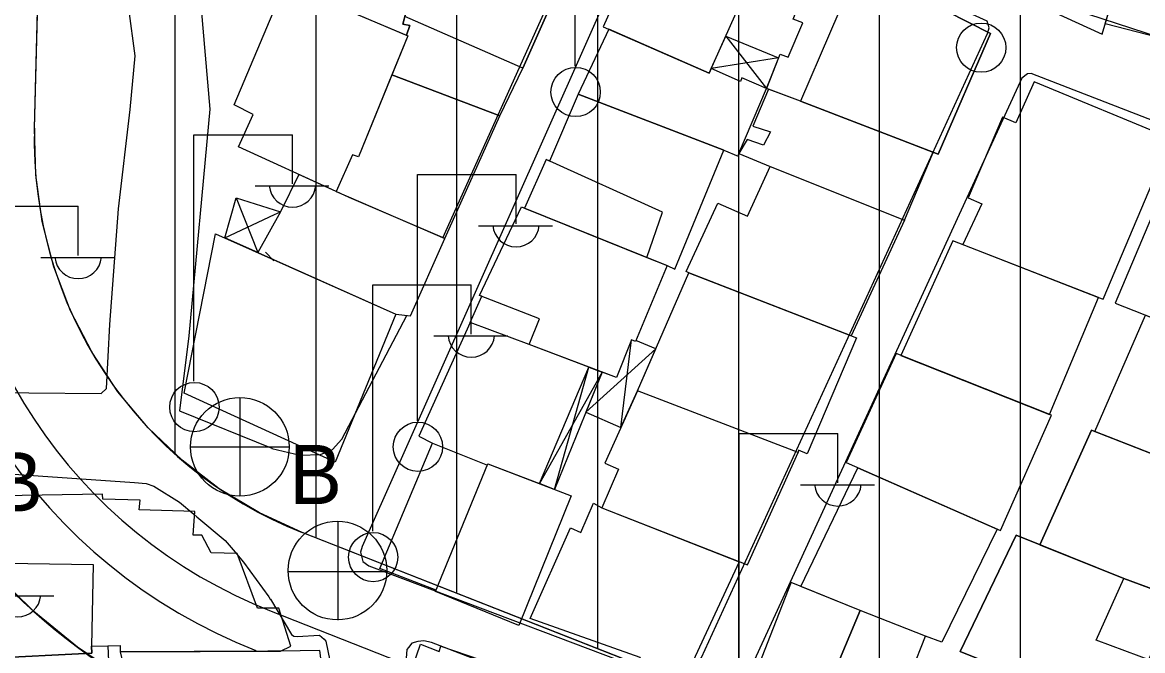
# Model space of a CAD drawing. Extents: x 417997 to 421451, y 4451742 to 4455216.
# Drawn here: x 419134.5 to 419214.1, y 4452750.1 to 4452794.7 of the extents above; entities that cross this region are included whole.
import ezdxf

# ---------------------------------------------------------------- set-up
doc = ezdxf.new("R2010")
doc.units = 0
for name, color, linetype in [('ADAKENARI', 7, 'Continuous'), ('B_Mesken', 7, 'Continuous'), ('B_Sundurma', 7, 'Continuous'), ('B_Teras', 7, 'Continuous'), ('KALDIRIM', 7, 'Continuous'), ('PL_KON_MEV_350', 7, 'Continuous'), ('S_Elektrik_Diregi', 7, 'Continuous'), ('S_Rogar_Kapagi', 7, 'Continuous'), ('S_Rogar_Kapagi_Buski', 7, 'Continuous'), ('TR_ORTAYOGUNKONUT', 7, 'Continuous'), ('Yol_Sose', 7, 'Continuous')]:
    doc.layers.add(name, color=color, linetype=linetype)

msp = doc.modelspace()

# ---------------------------------------------------------------- linework, layer by layer
at = {"layer": 'ADAKENARI'}
for p, q in [((419135.391, 4452787.233), (419139.641, 4452947.996)), ((419135.391, 4452787.233), (419139.641, 4452947.996)), ((419277.123, 4452710.286), (419154.406, 4452758.519)), ((419277.123, 4452710.286), (419154.406, 4452758.519))]:
    msp.add_line(p, q, dxfattribs=at)
for centre, radius, start in [((419165.38, 4452786.44), 30, 178.48545), ((419165.38, 4452786.44), 30, 178.48545), ((419165.38, 4452786.439), 44.999, 207.76938), ((419165.38, 4452786.439), 44.999, 207.76938)]:
    msp.add_arc(centre, radius, start, 248.54329, dxfattribs=at)
at = {"layer": 'B_Mesken'}
for points in [[(419203.777, 4452797.297), (419211.188, 4452793.894), (419215.412, 4452808.094), (419212.257, 4452809.448), (419211.214, 4452807.034), (419208.836, 4452808.231)], [(419221.91, 4452805.106), (419218.926, 4452792.696), (419211.405, 4452794.624), (419215.412, 4452808.094)], [(419157.817, 4452806.337), (419154.508, 4452796.927), (419161.797, 4452793.834), (419162.036, 4452794.503), (419161.552, 4452794.6), (419163.891, 4452803.407)], [(419175.774, 4452794.422), (419183.297, 4452791.138), (419187.756, 4452801.095), (419180.374, 4452804.709)], [(419170.076, 4452791.478), (419173.588, 4452799.428), (419173.29, 4452799.556), (419170.589, 4452800.51), (419163.891, 4452803.407), (419161.698, 4452795.15), (419161.552, 4452794.6), (419162.036, 4452794.503), (419161.797, 4452793.834), (419161.913, 4452793.785), (419160.775, 4452791.003), (419168.433, 4452788.097), (419170.076, 4452791.478), (419173.588, 4452799.428)], [(419189.784, 4452789.128), (419187.368, 4452790.033), (419188.326, 4452792.486), (419188.913, 4452792.259), (419189.94, 4452794.694), (419189.25, 4452794.955), (419191.132, 4452799.687), (419193.712, 4452798.305), (419193.893, 4452798.729), (419203.277, 4452793.934), (419199.551, 4452785.37)], [(419149.576, 4452788.878), (419152.595, 4452796.059), (419153.194, 4452797.485), (419161.913, 4452793.785), (419158.399, 4452785.195), (419157.985, 4452785.334), (419156.821, 4452782.73), (419149.877, 4452785.907), (419150.92, 4452788.184)], [(419176.18, 4452794.245), (419174.002, 4452789.641), (419184.34, 4452785.666), (419185.345, 4452785.229), (419185.413, 4452785.425), (419187.368, 4452790.033), (419185.617, 4452790.785), (419185.512, 4452790.542), (419183.436, 4452791.45), (419183.297, 4452791.138)], [(419164.536, 4452779.39), (419168.433, 4452788.097), (419160.775, 4452791.003), (419158.399, 4452785.195), (419157.985, 4452785.334), (419156.821, 4452782.73)], [(419210.931, 4452775.214), (419211.26, 4452775.092), (419216.088, 4452786.481), (419206.365, 4452790.52), (419205.058, 4452787.6), (419204.108, 4452788), (419201.685, 4452782.28), (419202.652, 4452781.862), (419201.313, 4452778.955)], [(419171.716, 4452785), (419170.182, 4452781.551), (419178.859, 4452778.054), (419180.314, 4452777.467), (419180.867, 4452777.224), (419184.34, 4452785.666), (419174.002, 4452789.641), (419171.965, 4452784.887)], [(419197.162, 4452780.693), (419199.209, 4452785.501), (419189.784, 4452789.128), (419187.501, 4452789.983), (419186.404, 4452787.358), (419187.647, 4452786.958), (419187.143, 4452786.025), (419186.004, 4452786.409), (419185.413, 4452785.425), (419187.619, 4452784.505)], [(419154.171, 4452783.942), (419152.863, 4452781.285), (419151.252, 4452778.391), (419161.056, 4452774.022), (419162.097, 4452773.907), (419164.536, 4452779.39), (419157.743, 4452782.3), (419156.821, 4452782.73)], [(419181.856, 4452776.948), (419181.666, 4452777.052), (419183.912, 4452781.904), (419186.017, 4452780.982), (419187.619, 4452784.505), (419197.162, 4452780.693), (419193.378, 4452772.494)], [(419212.11, 4452774.802), (419223.739, 4452770.243), (419226.789, 4452778.151), (419215.401, 4452782.588)], [(419170.52, 4452771.867), (419166.32, 4452773.418), (419167.166, 4452775.291), (419167.002, 4452775.356), (419169.981, 4452781.632), (419180.314, 4452777.467), (419178.064, 4452772.072), (419177.771, 4452772.211), (419176.706, 4452769.531), (419170.52, 4452771.867)], [(419148.241, 4452779.732), (419161.056, 4452774.022), (419156.751, 4452763.523), (419146.027, 4452768.405)], [(419207.463, 4452766.902), (419210.931, 4452775.214), (419200.586, 4452779.238), (419196.894, 4452771.095)], [(419178.217, 4452768.589), (419181.856, 4452776.948), (419193.748, 4452772.351), (419190.247, 4452764.114), (419189.643, 4452764.375), (419189.608, 4452764.202)], [(419166.32, 4452773.418), (419162.677, 4452765.36), (419163.649, 4452764.864), (419167.548, 4452763.298), (419167.593, 4452763.407), (419171.239, 4452761.998), (419174.745, 4452770.271), (419170.52, 4452771.867)], [(419223.519, 4452770.33), (419220.036, 4452762.026), (419210.684, 4452765.697), (419214.267, 4452773.956)], [(419193.018, 4452763.482), (419203.983, 4452758.66), (419207.59, 4452766.851), (419196.571, 4452771.223)], [(419175.683, 4452760.28), (419186.021, 4452756.224), (419189.608, 4452764.202), (419178.217, 4452768.589), (419175.884, 4452763.443), (419176.868, 4452763.008)], [(419219.73, 4452762.146), (419216.375, 4452753.915), (419214.798, 4452754.503), (419212.742, 4452755.269), (419206.773, 4452757.65), (419210.443, 4452765.784), (419218.252, 4452762.726)], [(419163.908, 4452754.429), (419159.924, 4452755.977), (419163.649, 4452764.864), (419167.548, 4452763.298), (419167.593, 4452763.407), (419173.49, 4452761.128), (419169.782, 4452751.93), (419163.867, 4452754.33)], [(419189.805, 4452754.697), (419193.84, 4452763.12), (419203.742, 4452758.767), (419199.807, 4452750.75), (419198.653, 4452751.167), (419194.015, 4452752.992)], [(419131.64, 4452761.092), (419131.795, 4452756.373), (419131.898, 4452749.573), (419139.482, 4452749.948), (419139.458, 4452750.45), (419140.61, 4452750.48), (419141.491, 4452750.505), (419141.49, 4452750.058), (419152.873, 4452750.094), (419153.603, 4452750.463), (419152.756, 4452753.146), (419151.238, 4452753.155), (419149.779, 4452757.023), (419147.938, 4452757.07), (419147.288, 4452758.324), (419146.665, 4452758.344), (419146.774, 4452760.021), (419142.821, 4452760.122), (419142.912, 4452760.824), (419140.244, 4452760.884), (419140.229, 4452761.25)], [(419185.437, 4452756.453), (419181.521, 4452748.043), (419178.655, 4452748.985), (419178.398, 4452749.642), (419170.579, 4452752.412), (419173.452, 4452758.854), (419174.194, 4452758.523), (419175.082, 4452760.595), (419175.683, 4452760.28)], [(419214.558, 4452749.472), (419214.843, 4452749.366), (419213.002, 4452745.318), (419201.123, 4452750.075), (419205.081, 4452758.325), (419212.742, 4452755.269), (419216.375, 4452753.915)], [(419190.46, 4452744.526), (419194.015, 4452752.992), (419189.111, 4452754.978), (419189.111, 4452754.995), (419185.746, 4452746.407)], [(419190.46, 4452744.526), (419197.677, 4452741.705), (419198.176, 4452743.003), (419199.659, 4452746.926), (419198.605, 4452747.275), (419198.989, 4452748.277), (419197.676, 4452748.713), (419198.653, 4452751.167), (419194.015, 4452752.992)], [(419130.9, 4452749.523), (419139.482, 4452749.948), (419139.458, 4452750.45), (419140.61, 4452750.48), (419140.701, 4452748.297), (419141.907, 4452748.326), (419143.247, 4452742.109), (419137.005, 4452741.649), (419131.43, 4452741.722)], [(419170.755, 4452748.234), (419167.677, 4452740.542), (419164.547, 4452741.739), (419164.596, 4452741.32), (419162.543, 4452742.19), (419161.824, 4452744.18), (419162.294, 4452745.389), (419161.155, 4452745.772), (419162.813, 4452750.607), (419164.124, 4452750.068), (419164.246, 4452750.465)], [(419155.653, 4452750.145), (419152.873, 4452750.094), (419151.955, 4452750.091), (419141.49, 4452750.058), (419141.907, 4452748.326), (419143.247, 4452742.109), (419144.885, 4452742.029), (419144.966, 4452744.507), (419146.227, 4452744.52), (419146.264, 4452743.556), (419148.989, 4452743.544), (419149.068, 4452742.212), (419151.866, 4452741.978), (419156.692, 4452742.403), (419156.057, 4452747.034)]]:
    msp.add_lwpolyline(points, close=True, dxfattribs=at)
at = {"layer": 'B_Sundurma'}
for p, q in [((419184.472, 4452793.762), (419187.368, 4452790.033)), ((419188.223, 4452792.221), (419183.436, 4452791.45)), ((419149.728, 4452782.27), (419151.252, 4452778.391)), ((419148.916, 4452779.432), (419152.435, 4452781.084)), ((419152.435, 4452781.084), (419152.863, 4452781.285)), ((419152.399, 4452777.804), (419151.798, 4452778.427)), ((419177.033, 4452765.978), (419177.771, 4452772.211)), ((419174.545, 4452767.057), (419179.516, 4452771.572)), ((419172.323, 4452761.579), (419174.745, 4452770.271)), ((419175.702, 4452769.91), (419171.239, 4452761.998))]:
    msp.add_line(p, q, dxfattribs=at)
for points in [[(419184.472, 4452793.762), (419188.223, 4452792.221), (419187.368, 4452790.033), (419185.617, 4452790.785), (419185.512, 4452790.542), (419183.436, 4452791.45)], [(419148.916, 4452779.432), (419149.728, 4452782.27), (419152.863, 4452781.285), (419151.252, 4452778.391)], [(419174.545, 4452767.057), (419177.033, 4452765.978), (419178.217, 4452768.589), (419179.516, 4452771.572), (419178.097, 4452772.149), (419178.064, 4452772.072), (419177.771, 4452772.211), (419176.706, 4452769.531), (419175.702, 4452769.91)], [(419175.702, 4452769.91), (419172.323, 4452761.579), (419171.239, 4452761.998), (419174.745, 4452770.271)]]:
    msp.add_lwpolyline(points, close=True, dxfattribs=at)
at = {"layer": 'B_Teras'}
for points in [[(419173.026, 4452799.649), (419173.588, 4452799.428), (419170.076, 4452791.478), (419161.698, 4452795.15), (419163.891, 4452803.407), (419170.589, 4452800.51)], [(419199.551, 4452785.37), (419203.277, 4452793.934), (419193.893, 4452798.729), (419189.784, 4452789.128)], [(419178.859, 4452778.054), (419179.994, 4452781.255), (419171.716, 4452785), (419170.182, 4452781.551)], [(419167.002, 4452775.356), (419169.981, 4452781.632), (419180.314, 4452777.467), (419178.064, 4452772.072), (419177.771, 4452772.211), (419176.706, 4452769.531), (419170.52, 4452771.867), (419171.253, 4452773.7)], [(419210.684, 4452765.697), (419210.443, 4452765.784), (419206.773, 4452757.65), (419212.742, 4452755.269), (419214.798, 4452754.503), (419218.252, 4452762.726)], [(419163.867, 4452754.33), (419167.593, 4452763.407), (419173.49, 4452761.128), (419169.782, 4452751.93)], [(419201.123, 4452750.075), (419213.002, 4452745.318), (419214.843, 4452749.366), (419210.779, 4452750.877), (419212.742, 4452755.269), (419205.081, 4452758.325)], [(419131.898, 4452749.573), (419131.795, 4452756.373), (419139.563, 4452756.255), (419139.458, 4452750.45), (419139.482, 4452749.948)], [(419191.585, 4452747.207), (419196.283, 4452745.569), (419195.62, 4452743.893), (419198.176, 4452743.003), (419199.659, 4452746.926), (419198.605, 4452747.275), (419198.989, 4452748.277), (419197.676, 4452748.713), (419198.653, 4452751.167), (419194.015, 4452752.992)]]:
    msp.add_lwpolyline(points, close=True, dxfattribs=at)
at = {"layer": 'KALDIRIM'}
msp.add_line((419152.212, 4452752.934), (419181.695, 4452741.346), dxfattribs=at)
msp.add_line((419152.212, 4452752.934), (419181.695, 4452741.346), dxfattribs=at)
for radius, end in [(38.999, 248.54341), (38.999, 248.54341), (36, 248.54361), (36, 248.54361)]:
    msp.add_arc((419165.38, 4452786.439), radius, 178.48545, end, dxfattribs=at)
at = {"layer": 'PL_KON_MEV_350'}
for points in [[(419338.263, 4452809.45), (419290.932, 4452715.558), (419277.123, 4452710.286), (419154.406, 4452758.519), (419151.377, 4452759.909), (419148.52, 4452761.626), (419145.872, 4452763.649), (419143.464, 4452765.954), (419141.327, 4452768.511), (419139.486, 4452771.29), (419137.966, 4452774.256), (419136.783, 4452777.373), (419135.954, 4452780.601), (419135.488, 4452783.901), (419135.391, 4452787.233), (419139.641, 4452947.996)], [(419141.767, 4452748.133), (419138.457, 4452750.382), (419135.36, 4452752.916), (419132.501, 4452755.716), (419129.902, 4452758.758), (419127.583, 4452762.019), (419125.563, 4452765.473), (419114.28, 4452765.095)]]:
    msp.add_lwpolyline(points, dxfattribs=at)
at = {"layer": 'S_Elektrik_Diregi'}
for p, q in [((419173.781, 4452791.626), (419173.781, 4452809.126)), ((419146.715, 4452769.26), (419146.715, 4452786.761)), ((419146.715, 4452786.761), (419153.715, 4452786.761)), ((419153.715, 4452783.261), (419153.715, 4452786.761)), ((419162.583, 4452766.442), (419162.583, 4452783.942)), ((419162.583, 4452783.942), (419169.583, 4452783.942)), ((419169.583, 4452780.442), (419169.583, 4452783.942)), ((419151.055, 4452783.121), (419156.305, 4452783.121)), ((419131.5, 4452781.686), (419138.5, 4452781.686)), ((419138.5, 4452778.186), (419138.5, 4452781.686)), ((419166.923, 4452780.302), (419172.173, 4452780.302)), ((419135.84, 4452778.046), (419141.09, 4452778.046)), ((419159.407, 4452758.613), (419159.407, 4452776.113)), ((419159.407, 4452776.113), (419166.407, 4452776.113)), ((419166.407, 4452772.613), (419166.407, 4452776.113)), ((419163.747, 4452772.473), (419168.997, 4452772.473)), ((419185.432, 4452748.049), (419185.432, 4452765.549)), ((419185.432, 4452765.549), (419192.432, 4452765.549)), ((419192.432, 4452762.049), (419192.432, 4452765.549)), ((419189.772, 4452761.909), (419195.023, 4452761.909)), ((419131.528, 4452754.034), (419136.778, 4452754.034))]:
    msp.add_line(p, q, dxfattribs=at)
for centre in [(419202.608, 4452792.937), (419173.817, 4452789.79), (419146.751, 4452767.425), (419162.619, 4452764.607), (419159.443, 4452756.777)]:
    msp.add_circle(centre, 1.75, dxfattribs=at)
for centre in [(419153.715, 4452783.273), (419169.584, 4452780.455), (419138.5, 4452778.199), (419166.408, 4452772.626), (419192.433, 4452762.062), (419134.189, 4452754.187)]:
    msp.add_arc(centre, 1.658, 184.83843, 355.14641, dxfattribs=at)
at = {"layer": 'S_Rogar_Kapagi'}
for p, q in [((419156.959, 4452752.293), (419156.959, 4452759.293)), ((419153.389, 4452755.758), (419160.389, 4452755.758))]:
    msp.add_line(p, q, dxfattribs=at)
msp.add_circle((419156.905, 4452755.821), 3.5, dxfattribs=at)
at = {"layer": 'S_Rogar_Kapagi_Buski'}
for p, q in [((419149.984, 4452768.106), (419149.984, 4452761.105)), ((419146.484, 4452764.605), (419153.484, 4452764.605))]:
    msp.add_line(p, q, dxfattribs=at)
msp.add_circle((419149.984, 4452764.605), 3.5, dxfattribs=at)
at = {"layer": 'TR_ORTAYOGUNKONUT'}
for p, q in [((419145.391, 4452764.109), (419145.391, 4452947.657)), ((419145.391, 4452764.109), (419145.391, 4452947.657)), ((419155.391, 4452758.132), (419155.391, 4452947.069)), ((419155.391, 4452758.132), (419155.391, 4452947.069)), ((419165.391, 4452754.202), (419165.391, 4452853.438)), ((419165.391, 4452754.202), (419165.391, 4452853.438)), ((419205.391, 4452738.48), (419205.391, 4452842.648)), ((419205.391, 4452738.48), (419205.391, 4452842.648)), ((419175.391, 4452750.271), (419175.391, 4452840.608)), ((419175.391, 4452750.271), (419175.391, 4452840.608)), ((419195.391, 4452742.41), (419195.391, 4452837.377)), ((419195.391, 4452742.41), (419195.391, 4452837.377)), ((419185.391, 4452746.341), (419185.391, 4452836.823)), ((419185.391, 4452746.341), (419185.391, 4452836.823))]:
    msp.add_line(p, q, dxfattribs=at)
at = {"layer": 'Yol_Sose'}
for points in [[(419142.543, 4452792.349), (419141.639, 4452799.109), (419140.818, 4452802.04), (419131.524, 4452829.371), (419130.835, 4452830.844), (419119.336, 4452843.682), (419118.332, 4452845.284), (419117.633, 4452847.096), (419117.266, 4452848.66), (419116.976, 4452850.162), (419116.763, 4452852.179), (419116.845, 4452854.726), (419118.048, 4452872.116), (419118.317, 4452874.259), (419119.3, 4452878.751), (419121.707, 4452887.225), (419121.7, 4452887.623), (419121.362, 4452888.251), (419120.855, 4452888.604), (419120.072, 4452889.025), (419115.615, 4452889.63)], [(419183.571, 4452808.322), (419203.225, 4452798.393), (419207.165, 4452796.308), (419218.289, 4452792.694), (419218.853, 4452792.673), (419219.277, 4452793.195), (419221.732, 4452804.833), (419225.958, 4452828.17), (419230.925, 4452856.32), (419232.857, 4452868.08), (419232.757, 4452868.483), (419232.496, 4452868.786), (419232.034, 4452869.069), (419217.009, 4452874.244), (419216.505, 4452874.084), (419216.122, 4452873.904), (419215.636, 4452873.099), (419212.187, 4452853.205), (419207.283, 4452825.659), (419203.907, 4452815.696)], [(419164.396, 4452779.45), (419171.333, 4452794.842), (419177.15, 4452807.757), (419177.256, 4452808.209), (419177.031, 4452808.697), (419176.667, 4452809.029), (419163.509, 4452816.214)], [(419145.699, 4452806.392), (419146.889, 4452799.543), (419147.851, 4452788.575), (419146.349, 4452772.473), (419145.698, 4452767.171), (419152.257, 4452764.499)], [(419114.318, 4452768.459), (419120.182, 4452768.72), (419134.988, 4452768.428), (419140.122, 4452768.398), (419140.511, 4452768.749), (419140.75, 4452773.283), (419141.367, 4452781.501), (419142.197, 4452788.552), (419142.543, 4452792.349)], [(419152.259, 4452764.498), (419154.25, 4452764.019), (419155.711, 4452764.067), (419156.563, 4452764.413), (419157.209, 4452765.159), (419161.826, 4452773.925)], [(419152.257, 4452764.499), (419152.258, 4452764.498)], [(419152.258, 4452764.498), (419152.259, 4452764.498)], [(419131.566, 4452749.524), (419131.107, 4452762.384), (419131.234, 4452762.58), (419131.377, 4452762.695), (419131.58, 4452762.789), (419131.881, 4452762.799), (419142.497, 4452762.078), (419143.334, 4452761.991), (419143.868, 4452761.814), (419145.699, 4452760.672)], [(419145.699, 4452760.672), (419146.704, 4452759.828)], [(419146.704, 4452759.828), (419146.933, 4452759.635)], [(419146.933, 4452759.635), (419148.94, 4452757.95), (419149.643, 4452757.12)], [(419149.643, 4452757.12), (419150.104, 4452756.574)], [(419150.104, 4452756.574), (419150.238, 4452756.416), (419152.038, 4452753.959), (419152.142, 4452753.785)], [(419152.142, 4452753.785), (419152.143, 4452753.784)], [(419152.143, 4452753.784), (419152.144, 4452753.782)], [(419152.144, 4452753.782), (419153.645, 4452751.277), (419153.801, 4452751.155), (419154.045, 4452751.137), (419155.644, 4452751.237), (419155.973, 4452750.958), (419156.094, 4452750.801), (419157.463, 4452744.189)]]:
    msp.add_lwpolyline(points, dxfattribs=at)
for points in [[(419161.528, 4452755.26), (419180.184, 4452748.22), (419180.757, 4452748.08), (419181.401, 4452748.339), (419181.975, 4452748.598), (419182.359, 4452748.98), (419182.743, 4452749.657), (419203.057, 4452793.937), (419203.18, 4452794.337), (419203.025, 4452794.807), (419180.694, 4452805.024), (419179.928, 4452804.991), (419179.667, 4452804.783), (419158.656, 4452757.538), (419158.533, 4452757.138), (419158.704, 4452756.459), (419159.138, 4452756.162)], [(419186.021, 4452745.791), (419207.657, 4452737.285), (419208.733, 4452737.126), (419209.029, 4452737.194), (419209.499, 4452737.575), (419226.584, 4452778.154), (419226.567, 4452778.311), (419226.377, 4452778.659), (419216.514, 4452782.441), (419215.976, 4452782.703), (419215.804, 4452783.139), (419215.788, 4452783.765), (419216.788, 4452786.301), (419216.824, 4452786.684), (419216.651, 4452787.032), (419206.146, 4452791.112), (419205.885, 4452791.078), (419205.484, 4452790.766), (419185.287, 4452746.818), (419185.251, 4452746.505), (419185.476, 4452746.122)], [(419167.25, 4452732.016), (419191.42, 4452722.614), (419218.367, 4452712.267), (419267.542, 4452693.74), (419267.941, 4452693.687), (419268.741, 4452693.754), (419278.57, 4452697.864), (419281.459, 4452699.351), (419283.027, 4452700.441), (419283.34, 4452700.805), (419284.425, 4452703.027), (419284.376, 4452703.984), (419284.064, 4452704.315), (419163.58, 4452750.712), (419163.042, 4452750.836), (419162.624, 4452750.785), (419162.19, 4452750.681), (419161.945, 4452750.369), (419161.841, 4452750.23), (419161.786, 4452749.604), (419164.937, 4452735.546), (419165.661, 4452733.527), (419166.058, 4452732.935), (419166.647, 4452732.342)]]:
    msp.add_lwpolyline(points, close=True, dxfattribs=at)

# ---------------------------------------------------------------- texts
at = {"layer": 'S_Rogar_Kapagi_Buski'}
for p in [(419153.484, 4452760.541), (419132.245, 4452760.021)]:
    msp.add_text('B', height=4.2, dxfattribs=at).set_placement(p)

doc.saveas('drawing.dxf')
